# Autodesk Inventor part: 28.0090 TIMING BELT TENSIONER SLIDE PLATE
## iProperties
Created: 2007-04
Part Number: 28.0090 TIMING BELT TENSIONER SLIDE PLATE
Material: Steel
Document SubType Name: Modeling
Designer: Andy Moles
Mass: 46.1643 g
Surface Area: 55.6643 cm^2
Volume: 5.8808 cm^3
Density: 7.85 g/cm^3
Author: Andy Moles
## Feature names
1. Extrusion1
2. Extrusion2
3. Extrusion3
